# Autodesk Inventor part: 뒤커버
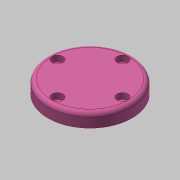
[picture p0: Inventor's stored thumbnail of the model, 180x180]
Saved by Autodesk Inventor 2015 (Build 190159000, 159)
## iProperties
Created: 2015-09
Part Number: 뒤커버
Material: 알루미늄 6061
Document SubType Name: Modeling
Designer: mduedu
Density: 1 g/cm^3
Appearance: 분홍색
Author: mduedu
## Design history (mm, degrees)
sketch "스케치1"
  geometry: L1 (0, 7.5)-(0, -7.5); L2 (0, 7.5)-(31, 7.5); L3 (31, 7.5)-(31, -2.5); L4 (31, -2.5)-(17.5, -2.5); L5 (17.5, -2.5)-(17.5, -7.5); L6 (17.5, -7.5)-(0, -7.5); 2 further points
  constraints: 12 end point, 2 parallel, 2 perpendicular, 1 coincident, 1 horizontal, 1 midpoint, 1 vertical
  dimensions: "d0" = 15 distance of L1.start L1.end; "d1" = 62 diameter of L3 L1; "d2" = 35 diameter of L5 L1; "d3" = 10 distance of L2.end L3.end
revolve "회전1" sketch "스케치1" stored, may be unused: angle "d4" = 90 deg
fillet "모깎기2" dims "d48" = 3
sketch "스케치4" dims "d49" = 48
  geometry: 3 further points
  constraints: 2 vertical alignment, 1 coincident, 2 other
hole "구멍4" sketch "스케치4" at (0, 24) diameter "d50" = 4.5; stored, may be unused: countersink angle "d54" = 90 deg, drill point angle "d56" = 118 deg; dims "d51" = 6, "d52" = 8, "d53" = 4.4, "d55" = 8
hole "구멍5" diameter "d62" = 24; stored, may be unused: countersink angle "d66" = 90 deg, drill point angle "d68" = 0 deg; dims "d60" = 10, "d61" = 10, "d63" = 6, "d64" = 4, "d65" = 2, "d67" = 8
fillet "모깎기3" dims "d69" = 3
chamfer "모따기3" distance "d43" = 1; stored, may be unused: second distance "d44" = 2, angle "d45" = 45 deg
node "솔리드1"
pattern_circular "원형 패턴1" dims angle "d58" = 360 deg
